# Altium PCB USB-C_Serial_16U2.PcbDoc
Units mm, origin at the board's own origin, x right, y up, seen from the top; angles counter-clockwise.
Board outline 17.78 x 24 mm, 2 copper layers (TOP, BOTTOM), stack 1.6 mm thick; 27 components, 31 nets, 144 pads, 39 vias.
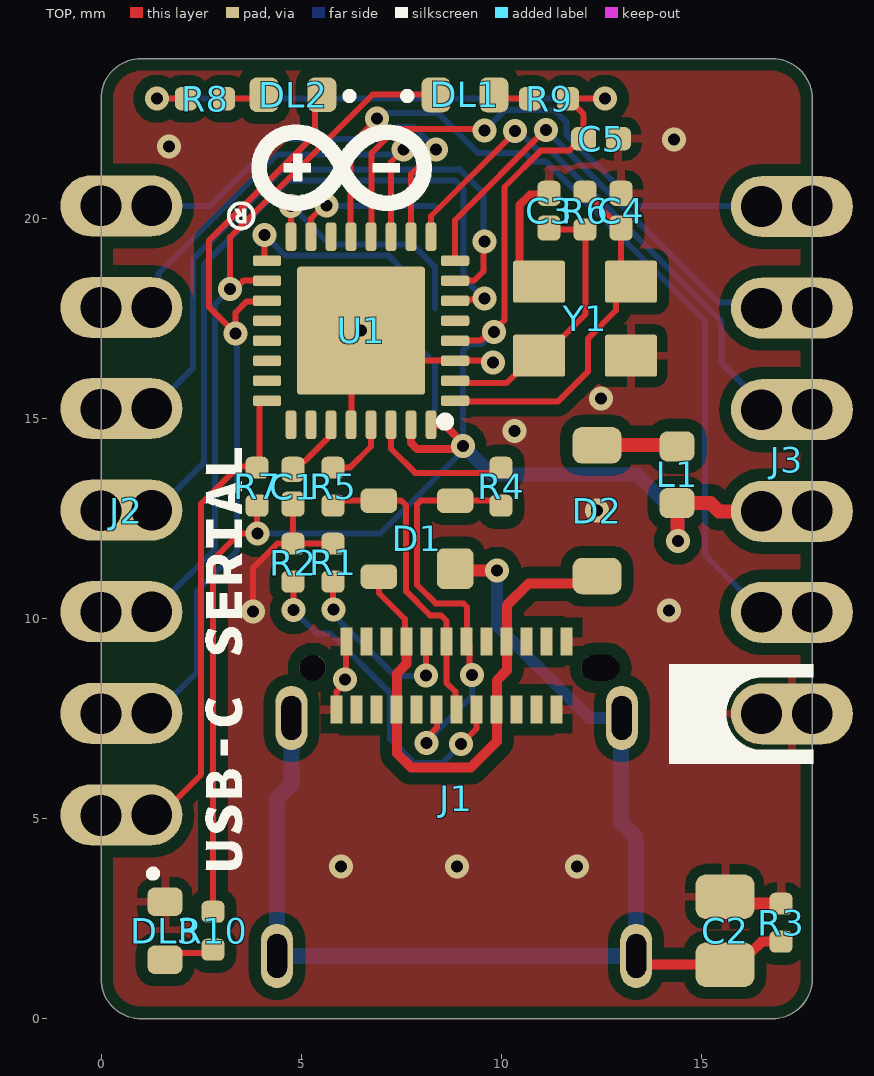
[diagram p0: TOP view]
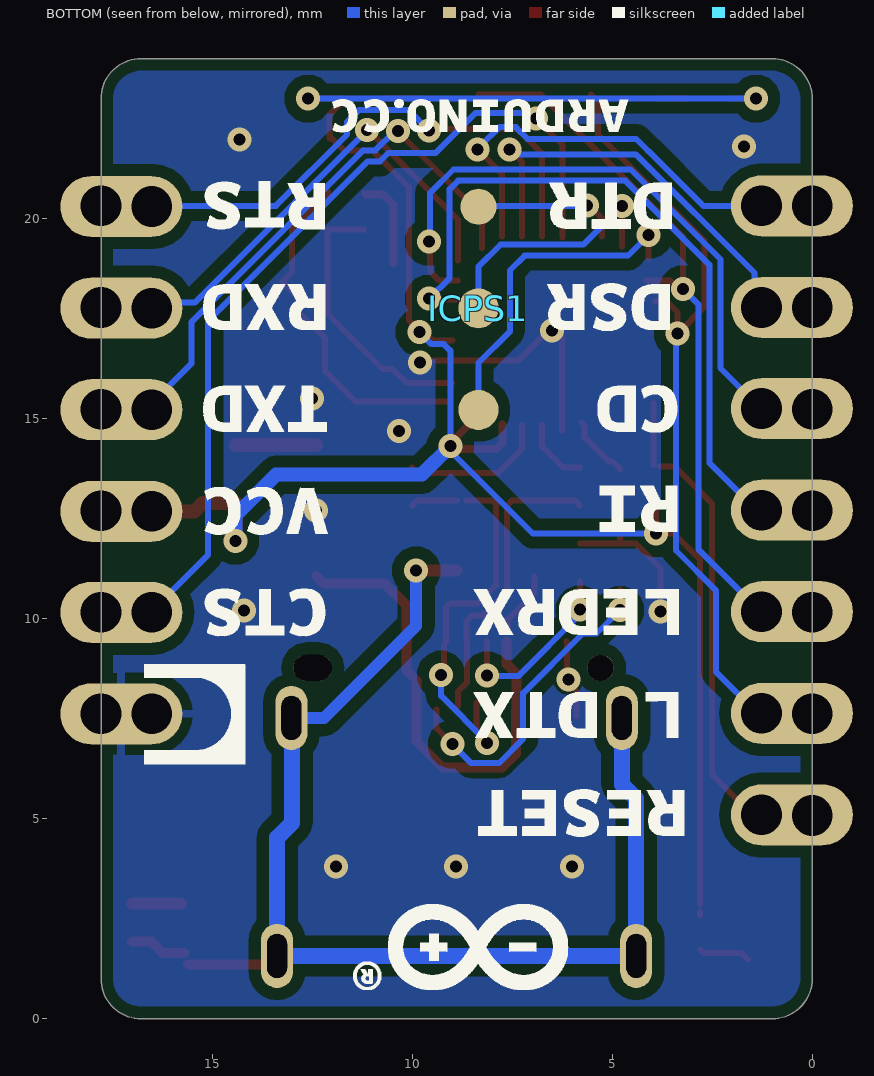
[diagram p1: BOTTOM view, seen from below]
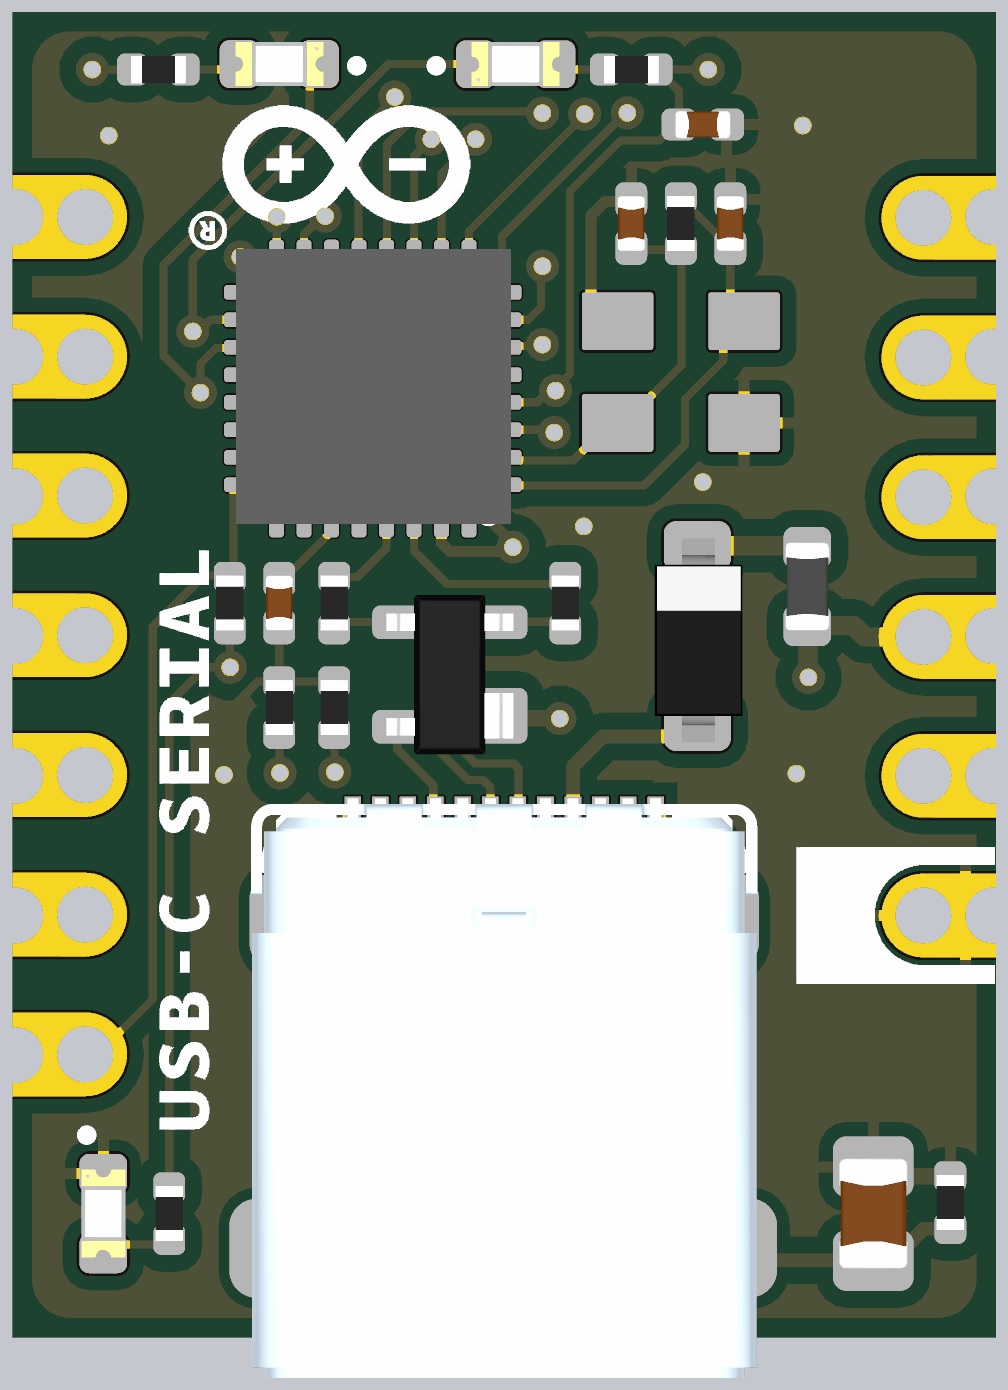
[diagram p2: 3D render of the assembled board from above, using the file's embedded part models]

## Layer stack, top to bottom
Top Solder: solder mask 0.0102, Solder Resist, Dk 3.5
TOP: signal copper 0.018
Dielectric2: core 1.564, FR-4, Dk 4.8
BOTTOM: signal copper 0.018
Bottom Solder: solder mask 0.0102, Solder Resist, Dk 3.5

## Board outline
1,0 cw(c1,1) 0,1 0,23 cw(c1,23) 1,24 16.78,24 cw(c16.78,23) 17.78,23 17.78,1 cw(c16.78,1) 16.78,0

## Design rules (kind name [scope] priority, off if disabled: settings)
BoardOutlineClearance Silks [(OnLayer('Top Overlay') OR OnLayer('Bottom Overlay'))] p1: gap=0.1 ignorepadtopadclearanceinfootprint=FALSE
BoardOutlineClearance [All] p2: gap=0.3 ignorepadtopadclearanceinfootprint=FALSE
Clearance COPPER_0.3mm [All] p1: gap=0.127 ignorepadtopadclearanceinfootprint=FALSE except(0.3: Arc-Fill Arc-Poly Arc-Region Track-Fill Track-Poly Track-Region SMDPad-Fill SMDPad-Poly SMDPad-Region THPad-Fill THPad-Poly THPad-Region Via-Fill Via-Poly Via-Region Fill-Fill Fill-Poly Fill-Region Poly-Poly Poly-Region Region-Region)
Clearance "Generic clearance 0.127mm" [All] p2: gap=0.127 ignorepadtopadclearanceinfootprint=FALSE
ComponentClearance [All] p1: gap=0.2 collisioncheckmode=3 verticalgap=0 showdistances=TRUE
DiffPairsRouting USB [InDifferentialPairClass('USB')] p1: maxlimit=0.15 minlimit=0.15 mostfreqgap=0.15 toplayer_minwidth=0.15 toplayer_maxwidth=0.21 toplayer_prefwidth=0.2 bottomlayer_minwidth=0.15 bottomlayer_maxwidth=0.21 bottomlayer_prefwidth=0.2 impedanceprofiledriven=TRUE impedanceprofileid={E6B00C31-4C8E-439C-824F-D2B2CDC26F9C} impedanceprofilevalue=90.000000 maxuncoupledlength=12.7
Height [All] p1: minheight=0 maxheight=30 prefheight=12.7
HoleSize [All] p1: absolutevalues=TRUE maxlimit=20 minlimit=0.3 maxpercent=80.000 minpercent=20.000
HoleToHoleClearance [All] p1: gap=0.25 allowstackedmicrovias=FALSE
MinimumAnnularRing [All] p1: minimumring=0.15
MinimumSolderMaskSliver [All] p1: minsoldermaskwidth=0.05
PlaneConnect [All] p1: pad.planeconnectstyle=Relief pad.reliefexpansion=0.508 pad.reliefentries=4 pad.reliefconductorwidth=0.254 pad.reliefairgap=0.254 via.planeconnectstyle=Direct via.reliefexpansion=0.508 via.reliefentries=4 via.reliefconductorwidth=0.254 via.reliefairgap=0.254
PolygonConnect [All] p1: thpad.connectstyle=Relief thpad.reliefconductorwidth=0.2 thpad.reliefentries=4 thpad.polygonreliefangle="90 Angle" thpad.airgapwidth=0.254 smdpad.connectstyle=Relief smdpad.reliefconductorwidth=0.2 smdpad.reliefentries=4 smdpad.polygonreliefangle="90 Angle" smdpad.airgapwidth=0.254 via.connectstyle=Direct via.reliefconductorwidth=0.254 via.reliefentries=4 via.polygonreliefangle="90 Angle" via.airgapwidth=0.254
RoomDefinition USB-C_Serial_16U2 [InComponentClass('USB-C_Serial_16U2')] p1: confinementstyle=ConfineIn formatcopy=TRUE lockcomponents=FALSE outline 0,-1.6 25.6,-1.6 25.6,23.6 0,23.6
RoutingVias StandardVias [All] p1: holewidth=0.3 width=0.6 viastyle="Through Hole" minholewidth=0.3 minwidth=0.6 maxholewidth=0.3 maxwidth=0.6
SMDToCorner [All] p1: distance=39370
SilkToSilkClearance [All] p1: silktosilkclearance=0.2
SilkToSolderMaskClearance [IsPad] p1: minsilkscreentomaskgap=0.15 clearancetoexposedcopper=TRUE
SolderMaskExpansion VIAtented [IsVia] p1: expansion=0.102 istentingtop=TRUE
SolderMaskExpansion [All] p2: expansion=0.05 istentingtop=FALSE
UnRoutedNet [All] p1: checkbadconnections=TRUE
ViasUnderSMD [All] p1: allowed=FALSE
Width StandardTraces [All] p1: maxlimit=5 minlimit=0.127 preferedwidth=0.15
20 further rules are at their usual default settings.

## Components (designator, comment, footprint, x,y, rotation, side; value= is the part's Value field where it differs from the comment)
C1 "C0402C105K8PACTU" CAP-0402 4.8,13.3 r270 top value=1µF
C2 "C0805C472KDRACTU" CAP-0805 15.6,2.2 r270 top value=4.7nF
C3 "C0402H100J5GACTU" CAP-0402 11.2,20.2 r270 top value=10pF
C4 "C0402H100J5GACTU" CAP-0402 13,20.2 r270 top value=10pF
C5 "C0402C104K4RACTU" CAP-0402 12.5,22 r180 top value=100nF
D1 "PRTR5V0U2X,215" SOT190P230X110-4N 7.9,12 r90 top
D2 "PMEG6020AELRX" SOD123-1 12.4,12.7 r270 top
DL1 "HSMD-C190" LEDC1608X80N-AK 9.098,23.097 r0 top
DL2 "HSMD-C190" LEDC1608X80N-AK 4.8,23.1 r180 top
DL3 "HSMG-C190" LEDC1608X80N-AK 1.6,2.2 r270 top
ICPS1 "PINHD-2X03-SM-TP" 2X03-TP 7.53,17.66 r270 bottom locked
J1 "12401598E4#2A" 12401598E4#2A 8.89,5.5 r0 top
J2 "PH1-07-UA" "CONN STRIP 2.54 PIN HEADER DIP 180° 1x 7 PIN GOLD FLASH castelleted" 1.27,20.32 r90 top
J3 "PH1-06-UA" "CONN STRP 2.54 PIN HEADER DIP 180° 1x X PIN GOLD FLASH" 16.51,7.62 r270 top
L1 "BLM18PG471SN1D" L-0603 14.4,13.6 r270 top
R1 "RC0402FR-075K1L" RES-0402 5.8,11.4 r270 top
R2 "RC0402FR-075K1L" RES-0402 4.8,11.4 r90 top
R3 "CRCW04021M00FKED" RES-0402 17,2.4 r270 top value=1M
R4 "CRCW040222R0JNEDC" RES-0402 10,13.3 r90 top value=22
R5 "CRCW040222R0JNEDC" RES-0402 5.8,13.3 r90 top value=22
R6 "CRCW04021M00FKED" RES-0402 12.1,20.2 r270 top value=1M
R7 "CRCW040210K0FKED" RES-0402 3.9,13.3 r270 top value=10k
R8 "CRCW0402330RJNED" RES-0402 2.6,23 r0 top value=330
R9 "CRCW0402330RJNED" RES-0402 11.2,23 r0 top value=330
R10 "CRCW0402330RJNED" RES-0402 2.8,2.2 r90 top value=330
U1 "ATMEGA16U2" ATMEL_QFN32 6.5,17.2 r180 top
Y1 "FTX16.000M12SM3S-30/30" CX3225SB16000D0GZJC1-Footprint-1 12.1,17.5 r180 top

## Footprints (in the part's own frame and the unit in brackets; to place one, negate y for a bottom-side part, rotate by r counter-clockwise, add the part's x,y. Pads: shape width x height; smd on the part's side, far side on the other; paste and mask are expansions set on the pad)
2X03-TP [mm]
  rrect100% 0.9x0.9 smd paste+0: 1(-2.64,-0.815)
  rrect100% 1x1 smd paste+0: 3(-0.1,-0.815) 5(2.44,-0.815)
12401598E4#2A [mm]
  oval 1x1.8 on Top Paste: 0(-4.499,-3.932) 0(-4.131,2.023) 0(4.131,2.026) 0(4.461,-3.925)
  round 0.65 hole 0.65 unplated mask+0.05: 0(-3.6,3.27)
  oval 0.95x0.65 hole 0.65 slot 0.95 at 0 deg unplated mask+0: 0(3.6,3.27)
  rect 0.3x0.7 smd mask+0.04: A1(-2.75,3.93) A2(-2.25,3.93) A3(-1.75,3.93) A4(-1.25,3.93) A5(-0.75,3.93) A6(-0.25,3.93) A7(0.25,3.93) A8(0.75,3.93) A9(1.25,3.93) A10(1.75,3.93) A11(2.25,3.93) A12(2.75,3.93) B1(2.5,2.23) B2(2,2.23) B3(1.5,2.23) B4(1,2.23) B5(0.5,2.23) B6(0,2.23) B7(-0.5,2.23) B8(-1,2.23) B9(-1.5,2.23) B10(-2,2.23) B11(-2.5,2.23) B12(-3,2.23)
  oval 0.8x1.6 hole 0.5 slot 1.1 at 90 deg: "SHIELD 1"(-4.13,2.02) "SHIELD 2"(4.13,2.02) "SHIELD 3"(-4.49,-3.93) "SHIELD 4"(4.49,-3.93)
  body extent -4.6,-6.3 4.6,4.25, height 3.3
ATMEL_QFN32 [mm]
  rrect50% 0.711x0.27 smd mask+0.03: 1(-2.351,1.75) 2(-2.351,1.25) 3(-2.351,0.75) 4(-2.351,0.25) 5(-2.351,-0.25) 6(-2.351,-0.75) 7(-2.351,-1.25) 8(-2.351,-1.75) 17(2.351,-1.75) 18(2.351,-1.25) 19(2.351,-0.75) 20(2.351,-0.25) 21(2.351,0.25) 22(2.351,0.75) 23(2.351,1.25) 24(2.351,1.75)
  rrect50% 0.27x0.711 smd mask+0.03: 9(-1.75,-2.351) 10(-1.25,-2.351) 11(-0.75,-2.351) 12(-0.25,-2.351) 13(0.25,-2.351) 14(0.75,-2.351) 15(1.25,-2.351) 16(1.75,-2.351) 25(1.75,2.351) 26(1.25,2.351) 27(0.75,2.351) 28(0.25,2.351) 29(-0.25,2.351) 30(-0.75,2.351) 31(-1.25,2.351) 32(-1.75,2.351)
  rrect5% 3.2x3.2 smd paste-3.302 mask+0.05: EXP(0,0)
  body extent -2.51,-2.54 2.49,2.46, height 0.85
CAP-0402 [mm] "Chip Capacitor, 2-Leads, Body  0402 (in) 1005 (mm), IPC Medium Density"
  rrect52% 0.63x0.58 smd mask+0: 1(-0.435,0) 2(0.435,0)
  body extent -0.5,-0.25 0.5,0.25, height 0.5
CAP-0805 [mm] "Chip Capacitor, Body 0805 imperial, 2.0x1.2mm, IPC Medium Density"
  rrect45% 1.11x1.47 smd mask+0: 1(-0.85,0) 2(0.85,0)
  body extent -1,-0.62 1,0.63, height 1.25
"CONN STRIP 2.54 PIN HEADER DIP 180° 1x 7 PIN GOLD FLASH castelleted" [mil]
  round 27.56 hole 40 mask+7.87: 1(0,50) 2(-100,50) 3(-200,50) 4(-300,50) 5(-400,50) 6(-500,50) 7(-600,50)
  oval 60x120 hole 40 copper offset 0,30 paste-100: 1(0,0) 2(-100,0) 3(-199.41,0) 4(-299.41,0) 5(-399.41,0) 6(-499.41,0) 7(-599.41,0)
  body extent -650,-49 51,49, height 79
"CONN STRP 2.54 PIN HEADER DIP 180° 1x X PIN GOLD FLASH" [mil]
  round 27.56 hole 40 mask+7.87: 1(0,50) 2(-100,50) 3(-200,50) 4(-300,50) 5(-400,50) 6(-500,50)
  oval 60x120 hole 40 copper offset 0,30 paste-100: 1(0,0) 2(-100,0) 3(-199.41,0) 4(-299.41,0) 5(-399.41,0) 6(-499.41,0)
  body extent -550,-49 51,49, height 79
CX3225SB16000D0GZJC1-Footprint-1 [mm]
  rrect10% 1.3x1.05 smd: 1(-1.15,-0.925) 2(1.15,-0.925) 3(1.15,0.925) 4(-1.15,0.925)
  body extent -1.59,-1.21 1.59,1.21, height 0.6
L-0603 [mm] "Chip Inductor - Body 0603 imperial,1.6x0.8mm, IPC High Density"
  rrect51% 0.75x0.87 smd mask+0: 1(-0.71,0) 2(0.71,0)
  body extent -0.8,-0.4 0.8,0.4, height 0.8
LEDC1608X80N-AK [mm]
  rrect50% 0.72x0.87 smd: A(0.725,0) C(-0.725,0)
  body extent -0.8,-0.4 0.8,0.4, height 0.79
RES-0402 [mm] "Chip Resistor, 2-Leads, Body  0402 (in) 1005 (mm), IPC Medium Density"
  rrect51% 0.55x0.58 smd mask+0: 1(-0.475,0) 2(0.475,0)
  body extent -0.5,-0.25 0.5,0.25, height 0.34
SOD123-1 [mm]
  rrect50% 0.91x1.22 smd: A(1.635,0) C(-1.635,0)
  body extent -1.78,-0.78 1.92,0.82, height 1.27
SOT190P230X110-4N [mm]
  rrect33% 1.01x0.91 smd paste+0 mask+0: 1(-0.75,-0.955)
  rrect49% 0.61x0.91 smd paste+0 mask+0: 2(0.95,-0.955) 3(0.95,0.955) 4(-0.95,0.955)
  body extent -1.45,-1.15 1.45,1.15, height 1

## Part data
C1: library part C0017-A.9, "CAP CHIP 0402 1uF 10V X5R 10%", Case Code (Imperial)=0402, Case Code (Metric)=1005, Dielectric=X5R, Manufacturer=KEMET, Manufacturer 2=AVX, Manufacturer Part Number 2=GRM155R61A105KE15D, Tolerance=10%, Voltage=10V
C2: library part C0059-A.9, "CAP CHIP 0805 4.7nF 1000V X7R 10%", Case Code (Imperial)=0805, Case Code (Metric)=2012, Dielectric=X7R, Manufacturer=KEMET, Tolerance=10%, Voltage=1kV
C3 C4: library part C0006-A.9, "CAP CHIP 0402 10pF 50V C0G 5%", Case Code (Imperial)=0402, Case Code (Metric)=1005, Dielectric=C0G, Manufacturer=KEMET, Manufacturer 2=AVX, Manufacturer Part Number 2=04025A100KAT2A, Tolerance=5%, Voltage=50V
C5: library part C0012-A.10, "CAP CHIP 0402 100nF 16V X7R 10%", Case Code (Imperial)=0402, Case Code (Metric)=1005, Dielectric=X7R, Manufacturer=KEMET, Manufacturer 2=AVX, Manufacturer Part Number 2=0402YC104KAT2A, Tolerance=10%, Voltage=16V
D1: library part D0025-A.3, "TVS ARRAY 4LIN.8kV 1pF SOT143B", Manufacturer=Nexperia
D2: library part D0026-A.3, "DIODE SCHOTTKY SMD 2A 60V SOD123FL", Forward Current=2A, Forward Voltage=0.6V, Manufacturer=Nexperia
DL1 DL2: library part L0007-A.6, "LED SMD 0603 ORANGE604 8mcd DIFF.", Manufacturer=Broadcom, Manufacturer 2=Kingbright, Manufacturer Part Number 2=KPT-1608SECK
DL3: library part L0009-A.4, "LED SMD 0603 GREEN/568 15mcd 120^", Manufacturer=Broadcom
ICPS1: library part J0066-A.3, "2X03 6 TEST POINTS"
J1: library part J0220-A.5, "CONN RCP USB3.1 TYPEC 24P SMD RA", Flammability Rating="UL94 V-0", Manufacturer="Amphenol ICC (Commercial Products)"
J2: library part J0311-A.8, "CONN STRIP 2.54 PIN HEADER DIP 180° 1x 7 PIN GOLD FLASH castelleted", Manufacturer="4 UCONN"
J3: library part J0310-A.3, "CONN STRP 2.54 PIN HEADER DIP 180° 1x6 PIN GOLD FLASH castellated", Manufacturer=4UCONN
L1: library part I0006-A.3, "FERRITE SMD 0603 470R 1A 0.2R", Case Code (Imperial)=0603, Case Code (Metric)=1608, Current=1A, DC Resistance (DCR)=200mR, Manufacturer=Murata, Max Operating Temperature=125°C, Min Operating Temperature=-55°C, Package Quantity=1, Test Frequency=100MHz, Tolerance=25%
R1 R2: library part R0210-A.6, "RES CHIP 0402 5K1 1% 1/16W", Case/Package=0402, Manufacturer=YAGEO, Tolerance=1%
R3 R6: library part R0058-A.5, "RES CHIP 0402 1M 1% 1/16W", Case Code (Imperial)=0402, Case Code (Metric)=1005, Manufacturer=Vishay, Manufacturer 2=Panasonic, Manufacturer Part Number 2=ERJ-2RKF1004X, Power=63mW, Tolerance=1%
R4 R5: library part R0010-A.5, "RES CHIP 0402 22R 5% 1/16W", Case Code (Imperial)=0402, Case Code (Metric)=1005, Manufacturer=Vishay, Manufacturer 2=Panasonic, Manufacturer Part Number 2=ERJ-2GEJ220X, Power=63mW, Tolerance=5%
R7: library part R0003-A.8, "RES CHIP 0402 10K 1% 1/16W", Case Code (Imperial)=0402, Case Code (Metric)=1005, Manufacturer=Vishay, Manufacturer 2=Panasonic, Manufacturer Part Number 2=ERJ-2RKF1002X, Power=63mW, Tolerance=1%
R8 R9: library part R0017-A.8, "RES CHIP 0402 330R 5% 1/16W", Case Code (Imperial)=0402, Case Code (Metric)=1005, Manufacturer=Vishay, Manufacturer 2=Panasonic, Manufacturer Part Number 2=ERJ-2GEJ331X, Power=63mW, Tolerance=5%
R10: library part R0017-A.5, "RES CHIP 0402 330R 5% 1/16W", Case Code (Imperial)=0402, Case Code (Metric)=1005, Manufacturer=Vishay, Manufacturer 2=Panasonic, Manufacturer Part Number 2=ERJ-2GEJ331X, Power=63mW, Tolerance=5%
U1: library part U0035-A.7, "IC ATMEGA16U2", Manufacturer=Microchip
Y1: library part X0019-A.8, "CRYSTAL 16.0000MHZ 8PF SMD", Frequency=16MHz, Manufacturer="Fronter Electronics"

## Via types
v1: diameter 0.6, hole 0.3, TOP to BOTTOM, tented both sides, 39 vias

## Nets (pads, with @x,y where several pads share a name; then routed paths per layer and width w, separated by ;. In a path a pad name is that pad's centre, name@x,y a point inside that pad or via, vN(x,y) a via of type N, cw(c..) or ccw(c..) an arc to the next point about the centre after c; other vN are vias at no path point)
CD: J2.4 U1.6 | length 17.8
  TOP w0.15: U1.6@8.875,17.975 9.558,17.975 v1(9.583,17.999)
  BOTTOM w0.15: J2.4@1.371,12.7 2.571,13.899 2.571,18.849 4.674,20.953 8.854,20.953 9.067,20.74 9.067,18.516 v1(9.583,17.999)
CTS: J3.2 U1.13 | length 21.5
  TOP w0.15: U1.13@6.242,19.531 6.242,21.842 v1(6.9,22.5)
  BOTTOM w0.15: v1(6.9,22.5) 7.022,22.5 7.167,22.646 8.414,22.646 9.414,21.646 10.592,21.646 10.806,21.433 11.113,21.433 15.1,17.446 15.1,11.6 J3.2@16.525,10.175
D+: D1.3 J1.A6 J1.B6 R5.1 | length 7.7
  TOP w0.15: R5.1 5.932,12.957 D1.3@6.938,12.957 ; D1.3@6.938,12.957 7.5,12.957 7.626,12.831 7.626,10.682 8.224,10.084 8.498,10.084 8.64,9.942 J1.A6 ; J1.A6@8.635,9.43 8.635,8.404 8.859,8.18 8.859,7.814 J1.B6@8.921,7.751
D-: D1.2 J1.A7 J1.B7 R4.1 | length 10.5
  TOP w0.15: v1(8.133,6.892) 8.133,7.014 8.394,7.275 J1.B7@8.394,7.904 ; D1.2@8.655,12.95 7.991,12.95 7.903,12.862 7.903,10.844 8.365,10.382 9.062,10.382 9.15,10.294 J1.A7@9.15,9.44 ; D1.2@8.864,12.959 9.866,12.959 R4.1 ; J1.A7@9.143,9.43 9.209,9.364 9.209,8.665 v1(9.278,8.596)
  BOTTOM w0.15: v1(8.133,6.892) 8.133,6.927 9.278,8.071 v1(9.278,8.596)
DSR: J2.2 U1.11 | length 10.9
  TOP w0.15: U1.11 7.25,21.419 v1(7.563,21.732)
  BOTTOM w0.15: J2.2@1.27,17.78 1.442,17.952 1.442,18.642 4.4,21.6 7.6,21.6 v1@7.768,21.768
DTR: J2.1 U1.10 | length 10.6
  TOP w0.15: U1.10 7.75,21.112 v1(8.37,21.732)
  BOTTOM w0.15: J2.1@1.27,20.32 2.72,20.32 4.099,21.699 4.107,21.699 4.406,21.998 7.119,21.998 7.411,22.291 7.823,22.291 v1@8.305,21.809 ; v1(8.37,21.732) 8.394,21.732 8.471,21.809 v1@8.484,21.809
GND: C1.2 C2.1 C3.1 C4.1 C5.1 DL3.C J1.A1 J1.A12 J1.B1 J1.B12 J3.1 R1.1 R2.2 R3.1 U1.3 U1.28 U1.EXP Y1.2 Y1.4 | length 15.7
  TOP w0.15: v1(3.794,10.178) 3.794,11.259 4.41,11.875 R2.2 ; C1.2 R2.2 ; R1.1 R2.2 ; J1.B12@5.89,7.555 J1.B12 5.89,8.18 6.098,8.388 v1(6.098,8.483) 6.126,8.512 6.126,9.416 J1.A1 ; U1.28@6.257,14.71 U1.EXP@6.257,17.043 ; U1.EXP@6.6,17.2 7.35,16.45 U1.3 9.75,16.45 v1(9.8,16.4) ; C3.1@11.165,20.6 C3.1
  TOP w0.2: Y1.2@10.463,18.875 10.463,20.341 10.722,20.6 C3.1@11.165,20.6
  TOP w0.3: C2.1@15.775,2.875 R3.1
  BOTTOM w0.15: v1(6.098,8.483) v1@6.098,8.488
  other v1: 6,3.8 8.9,3.8 11.9,3.8 14.2,10.2 12.4,12.7 10.336,14.693 12.5,15.5 6.5,17.2 1.7,21.8 14.318,21.982
LED_RX: DL1.C J2.5 U1.18 | length 17.8
  TOP w0.15: U1.18 3.561,18.45 3.552,18.441 3.54,18.441 3.338,18.238 v1(3.227,18.238) 3.227,19.542 6.785,23.1 8.345,23.1 DL1.C@8.348,23.097
  BOTTOM w0.15: J2.5@1.27,10.16 2.848,11.738 2.848,17.859 v1(3.227,18.238)
LED_TX: DL2.C J2.6 U1.19 | length 19
  TOP w0.15: U1.19@3.935,17.936 3.647,17.936 3.367,17.655 v1(3.367,17.126) 2.695,17.798 2.695,19.45 5.355,22.109 5.355,22.93 DL2.C
  BOTTOM w0.15: J2.6@1.357,7.62 2.4,8.663 2.4,10.7 3.405,11.705 3.405,17.088 v1(3.367,17.126)
MISO: ICPS1.5 U1.17 | length 8.2
  TOP w0.15: U1.17@4.089,19.01 v1(4.089,19.594)
  BOTTOM w0.15: v1(4.089,19.594) 4.607,19.076 7.191,19.076 7.561,18.705 7.561,17.177 8.345,16.394 ICPS1.5
MOSI: ICPS1.3 U1.16 | length 6.3
  TOP w0.15: U1.16@4.75,19.309 4.752,19.311 4.752,20.321 v1(4.754,20.323)
  BOTTOM w0.15: v1(4.754,20.323) 5.724,19.353 7.793,19.353 8.345,18.801 ICPS1.3
NetC1_1: C1.1 U1.27 | length 1.6
  TOP w0.15: C1.1 4.993,13.928 5.079,13.928 5.69,14.539 5.69,14.819 U1.27@5.76,14.889
NetC2_2: "J1.SHIELD 1" "J1.SHIELD 2" "J1.SHIELD 3" "J1.SHIELD 4" C2.2 D1.1 R3.2 | length 31
  TOP w0.25: 13.21,1.35 C2.2 ; C2.2@15.693,1.643 16.235,1.643 16.517,1.925 R3.2
  TOP w0.3: D1.1@8.896,11.209 v1@9.891,11.209
  BOTTOM w0.15: 12.99,1.57 13,1.58
  BOTTOM w0.3: v1(9.9,11.2) 9.9,9.823 12.203,7.52 13.002,7.52
  BOTTOM w0.4: 4.76,7.52 4.76,5.86 4.4,5.5 4.4,1.57 12.99,1.57 ; 13.002,7.52 13.002,4.898 13.375,4.525 13.375,1.575
NetC3_2: C3.2 R6.2 U1.2 Y1.3 | length 6.8
  TOP w0.15: U1.2@9,15.892 10.142,15.892 10.493,16.243 Y1.3@10.691,16.243 ; Y1.3@10.743,16.243 11.525,17.025 11.525,17.029 12.113,17.617 12.113,19.725 R6.2 C3.2@11.206,19.725
NetC4_2: C4.2 R6.1 U1.1 Y1.1 | length 8.8
  TOP w0.15: U1.1@9.047,15.436 11.427,15.436 12.176,16.185 12.176,17.011 12.871,17.705 12.871,18.046 Y1.1 13,18.675 C4.2 ; R6.1 12.1,20.657 C4.2@12.992,19.765
NetD2_C: D2.C L1.1 | length 2.1
  TOP w0.15: D2.C D2.C@12.456,14.391
  TOP w0.35: D2.C@12.4,14.344 L1.1@14.4,14.344
NetDL1_A: DL1.A R9.1 | length 1
  TOP w0.15: DL1.A@9.775,23 R9.1@10.775,23
NetDL2_A: DL2.A R8.2 | length 0.7
  TOP w0.15: R8.2@3.13,23 DL2.A@3.8,23
NetDL3_A: DL3.A R10.1 | length 1.3
  TOP w0.15: DL3.A 1.763,1.638 2.713,1.638 R10.1
NetJ1_A5: J1.A5 R1.2 | length 4.6
  TOP w0.15: R1.2 5.805,10.92 5.805,10.23 v1(5.809,10.225) ; v1(8.128,8.579) 8.128,9.418 J1.A5
  BOTTOM w0.15: v1(5.809,10.225) 5.809,10.106 7.341,8.574 8.123,8.574 v1(8.128,8.579)
NetJ1_B5: J1.B5 R2.1 | length 8.2
  TOP w0.15: R2.1@4.806,10.73 4.806,10.218 v1(4.812,10.212) ; v1@8.999,6.866 9.39,7.256 J1.B5
  BOTTOM w0.15: v1(4.812,10.212) 5.394,9.63 5.738,9.63 7.226,8.141 7.226,6.995 7.831,6.39 8.527,6.39 v1(8.999,6.863)
NetR4_2: R4.2 U1.30 | length 3.7
  TOP w0.15: U1.30 7.25,14.251 7.854,13.647 9.872,13.647 R4.2
NetR5_2: R5.2 U1.29 | length 1.7
  TOP w0.15: R5.2 6.218,13.775 6.75,14.307 U1.29
RI: J2.3 U1.7 | length 15.2
  TOP w0.15: U1.7 9.325,18.45 9.56,18.685 9.56,19.4 v1(9.585,19.425)
  BOTTOM w0.15: J2.3@1.43,15.4 2.294,16.264 2.294,18.985 4.539,21.23 8.968,21.23 9.561,20.638 9.561,19.449 v1(9.585,19.425)
RST: J2.7 R7.1 U1.24 | length 11.9
  TOP w0.15: J2.7@1,5.1 1.5,5.1 2.5,6.1 2.5,12.87 3.43,13.8 R7.1@3.817,13.8 ; R7.1@3.966,13.841 U1.24@3.966,15.39
RTS: J3.6 U1.12 | length 13.5
  TOP w0.15: U1.12@6.76,19.561 6.76,21.639 7.36,22.239 9.552,22.239 v1(9.584,22.207)
  BOTTOM w0.15: v1(9.584,22.207) 10.091,22.714 11.336,22.714 11.63,22.42 11.63,22.102 13.412,20.32 J3.6@16.51,20.32
RXD: J3.5 U1.8 | length 11.4
  TOP w0.15: U1.8 8.851,19.967 11.096,22.212 v1(11.128,22.212)
  BOTTOM w0.15: v1(11.128,22.212) 15.44,17.9 16.375,17.9 J3.5@16.51,17.765
SCLK: ICPS1.1 U1.15 | length 3.6
  TOP w0.15: U1.15 5.25,20.006 v1@5.579,20.335
  BOTTOM w0.15: v1(5.634,20.335) 5.651,20.318 8.327,20.318 ICPS1.1
TXD: J3.4 U1.9 | length 13.5
  TOP w0.15: U1.9@8.25,19.274 U1.9 8.25,20.067 10.352,22.169 v1(10.352,22.191)
  BOTTOM w0.15: v1(10.352,22.191) 10.439,22.191 10.92,21.71 11.228,21.71 15.514,17.424 15.514,16.386 J3.4@16.592,15.308
VBUS: D1.4 D2.A J1.A4 J1.A9 J1.B4 J1.B9 | length 13.5
  TOP w0.15: D1.4 6.945,10.642 7.6,9.987 J1.A4@7.6,9.688
  TOP w0.25: J1.B9 7.401,7.719 7.401,6.632 7.754,6.279 9.244,6.279 9.895,6.93 J1.B4@9.895,7.73 ; J1.B9@7.398,7.73 7.398,8.63 7.64,8.872 J1.A4 ; J1.B4 9.894,7.734 9.894,8.459 10.145,8.71 J1.A9@10.145,9.426 ; J1.A9@10.145,9.435 10.145,10.335 10.685,10.875 12.21,10.875 D2.A
VCC: C5.2 J3.3 L1.2 R7.2 R8.1 R9.2 R10.2 U1.4 U1.31 U1.32 | length 53.9
  TOP w0.15: v1(1.4,23) R8.1@2,23 ; R10.2@2.8,2.575 R10.2 ; R10.2@2.8,2.856 2.8,11.475 3.456,12.131 v1(3.907,12.131) 3.903,12.134 3.903,12.822 R7.2 ; U1.4@8.99,16.95 9.488,16.95 9.7,17.163 v1(9.822,17.163) 9.822,17.203 10.085,17.466 10.085,19.215 10.087,19.217 10.087,20.794 11.003,21.71 11.711,21.71 12.001,22 C5.2 12.065,22.61 R9.2 ; R9.2@11.7,23 v1(12.6,23)
  TOP w0.2: U1.31@7.746,14.852 7.746,14.398 7.902,14.242 8.973,14.242 v1(9.047,14.315) 9.047,14.388 8.585,14.849 U1.32
  TOP w0.35: v1(14.421,11.948) 14.411,11.958 14.411,12.879 L1.2 15.24,12.89 15.445,12.685 J3.3@16.51,12.685
  BOTTOM w0.15: v1(1.4,23) 1.402,23.002 12.598,23.002 v1(12.6,23) ; v1(3.907,12.131) 6.984,12.131 v1@9.047,14.194 ; v1(9.047,14.315) 9.047,16.703 9.209,16.864 9.524,16.864 v1(9.822,17.163)
  BOTTOM w0.35: v1(9.047,14.315) 9.762,13.6 13.4,13.6 14.421,12.579 v1(14.421,11.948)
pads on no net: J1.0 J1.A2 J1.A3 J1.A8 J1.A10 J1.A11 J1.B2 J1.B3 J1.B8 J1.B10 J1.B11 U1.5 U1.14 U1.20 U1.21 U1.22 U1.23 U1.25 U1.26

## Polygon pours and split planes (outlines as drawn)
GND on BOTTOM "NONET_L-01_P-001" (solid, pour order 0): 17.78,0 17.78,24 -0.009,24 -0.009,0 -0.009,12.7 -0.009,0
GND on TOP "NONET_L-01_P-001" (solid, remove dead copper, pour order 1): 0,-0.043 17.78,-0.043 17.78,24 0,24

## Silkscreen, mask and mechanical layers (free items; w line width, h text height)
Top Overlay:
  drawing of 21 lines, arcs and shapes, not listed
Bottom Overlay:
  drawing of 55 lines, arcs and shapes, not listed
Route Tool Path:
  lines w2: 1,-1 cw(c1,1) -1,1 -1,23 cw(c1,23) 1,25 ; 16.78,-1 ccw(c16.78,1) 18.78,1 18.78,23 ccw(c16.78,23) 16.78,25
Board:
  the board outline again, w0.1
